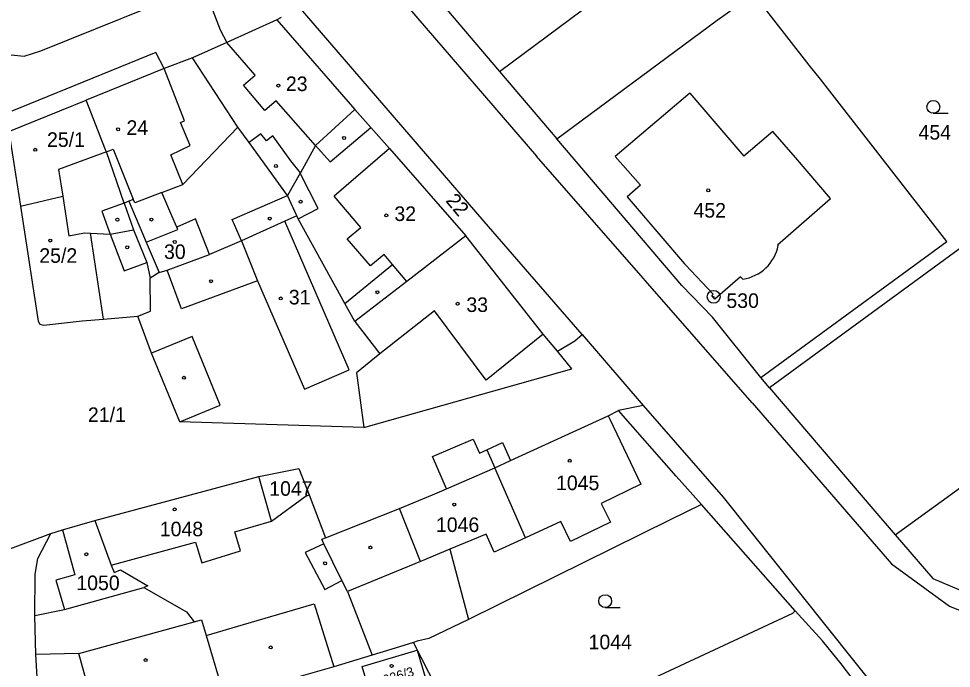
# Model space of a CAD drawing. Extents: x -736345 to -729997, y -1130177 to -1122501.
# Drawn here: x -733562.4 to -733453.6, y -1127040.9 to -1126965.1 of the extents above; entities that cross this region are included whole.
import ezdxf

# ---------------------------------------------------------------- set-up
doc = ezdxf.new("R2010")
doc.units = 0
for name, color, linetype in [('Vrstva 1', 7, 'Continuous'), ('Vrstva 17', 7, 'Continuous'), ('Vrstva 18', 7, 'Continuous'), ('Vrstva 19', 7, 'Continuous'), ('Vrstva 25', 7, 'Continuous'), ('Vrstva 4', 7, 'Continuous')]:
    doc.layers.add(name, color=color, linetype=linetype)

msp = doc.modelspace()

# ---------------------------------------------------------------- linework, layer by layer
at = {"layer": 'Vrstva 1'}
for points in [[(-733529.95, -1126948.76), (-733501.99, -1126981.18)], [(-733559.85, -1126968.91), (-733540.91, -1126961.22)], [(-733540.91, -1126961.22), (-733538.92, -1126966.43)], [(-733514.48, -1126961.65), (-733506.31, -1126971.3)], [(-733506.31, -1126971.3), (-733495.26, -1126963.12)], [(-733480.91, -1126965.32), (-733476.66, -1126962.26)], [(-733470.18, -1126970.55), (-733476.66, -1126962.26)], [(-733508.11, -1126988.8), (-733530.02, -1126963.43)], [(-733532.3, -1126965.28), (-733538.15, -1126967.92)], [(-733531.8, -1126965.01), (-733532.3, -1126965.28)], [(-733532.3, -1126965.28), (-733523.2, -1126975.75)], [(-733499.63, -1126979.17), (-733480.91, -1126965.32)], [(-733538.92, -1126966.43), (-733538.15, -1126967.92)], [(-733538.15, -1126967.92), (-733542.14, -1126969.72)], [(-733563.29, -1126969.37), (-733561.8, -1126969.5)], [(-733546.42, -1126969.09), (-733563.24, -1126975.94)], [(-733561.8, -1126969.5), (-733559.85, -1126968.91)], [(-733545.47, -1126970.94), (-733546.42, -1126969.09)], [(-733542.14, -1126969.72), (-733545.47, -1126970.94)], [(-733536.86, -1126977.79), (-733542.14, -1126969.72)], [(-733468.88, -1126972.22), (-733470.18, -1126970.55)], [(-733545.47, -1126970.94), (-733554.57, -1126974.66)], [(-733506.31, -1126971.3), (-733499.63, -1126979.17)], [(-733454.12, -1126991.13), (-733468.88, -1126972.22)], [(-733563.57, -1126978.3), (-733554.57, -1126974.66)], [(-733552.28, -1126980.44), (-733554.57, -1126974.66)], [(-733523.2, -1126975.75), (-733527.78, -1126979.95)], [(-733523.2, -1126975.75), (-733521.35, -1126977.82)], [(-733563.57, -1126978.3), (-733562.23, -1126987.02)], [(-733536.86, -1126977.79), (-733543.26, -1126984.48)], [(-733535.55, -1126979.58), (-733536.86, -1126977.79)], [(-733521.35, -1126977.82), (-733519.16, -1126980.27)], [(-733493.32, -1126986.55), (-733499.63, -1126979.17)], [(-733552.18, -1126980.67), (-733552.28, -1126980.44)], [(-733531.06, -1126985.78), (-733535.55, -1126979.58)], [(-733527.78, -1126979.95), (-733529.55, -1126983.11)], [(-733519.16, -1126980.27), (-733510.25, -1126990.48)], [(-733550.11, -1126986.66), (-733552.18, -1126980.67)], [(-733476.86, -1127009.96), (-733501.99, -1126981.18)], [(-733529.6, -1126983.18), (-733531.06, -1126985.78)], [(-733529.55, -1126983.11), (-733529.6, -1126983.18)], [(-733440.2, -1126982.91), (-733474.82, -1127008.2)], [(-733545.74, -1126985.43), (-733543.26, -1126984.48)], [(-733562.23, -1126987.02), (-733557.29, -1126985.83)], [(-733557.29, -1126985.83), (-733556.56, -1126990.46)], [(-733545.74, -1126985.43), (-733548.88, -1126986.63)], [(-733529.99, -1126988.14), (-733531.06, -1126985.78)], [(-733562.23, -1126987.02), (-733560.16, -1127000.41)], [(-733549.57, -1126986.43), (-733550.11, -1126986.66)], [(-733550.11, -1126986.66), (-733549.04, -1126989.78)], [(-733549.57, -1126986.43), (-733549.06, -1126986.21)], [(-733548.88, -1126986.63), (-733549.06, -1126986.21)], [(-733485.03, -1126996.26), (-733493.32, -1126986.55)], [(-733529.99, -1126988.14), (-733531.36, -1126988.77)], [(-733529.8, -1126988.49), (-733529.99, -1126988.14)], [(-733531.36, -1126988.77), (-733536.43, -1126991.07)], [(-733524.37, -1126998.35), (-733529.8, -1126988.49)], [(-733496.67, -1127001.99), (-733508.11, -1126988.8)], [(-733556.56, -1126990.46), (-733554.73, -1126990.12)], [(-733554.73, -1126990.12), (-733554.06, -1126990.15)], [(-733554.06, -1126990.15), (-733551.77, -1126990.26)], [(-733551.77, -1126990.26), (-733549.04, -1126989.78)], [(-733549.04, -1126989.78), (-733547.48, -1126993.57)], [(-733536.43, -1126991.07), (-733540.18, -1126992.64)], [(-733510.25, -1126990.48), (-733517.12, -1126995.78)], [(-733501.22, -1127001.93), (-733510.25, -1126990.48)], [(-733475.84, -1127007.01), (-733454.12, -1126991.13)], [(-733547.48, -1126993.57), (-733547.1, -1126995.4)], [(-733545.09, -1126994.48), (-733540.18, -1126992.64)], [(-733546.03, -1126994.76), (-733547.1, -1126995.4)], [(-733546.03, -1126994.76), (-733545.09, -1126994.48)], [(-733547.03, -1126999.25), (-733547.1, -1126995.4)], [(-733517.12, -1126995.78), (-733523.2, -1127000.47)], [(-733485.03, -1126996.26), (-733481.49, -1126999.96)], [(-733523.2, -1127000.47), (-733524.37, -1126998.35)], [(-733555, -1127000.4), (-733552.52, -1127000.18)], [(-733552.52, -1127000.18), (-733548.54, -1126999.83)], [(-733548.54, -1126999.83), (-733547.03, -1126999.25)], [(-733546.94, -1127004.15), (-733548.54, -1126999.83)], [(-733475.84, -1127007.01), (-733481.49, -1126999.96)], [(-733560.16, -1127000.41), (-733559.95, -1127000.77)], [(-733559.95, -1127000.77), (-733559.51, -1127000.9)], [(-733559.51, -1127000.9), (-733555, -1127000.4)], [(-733523.2, -1127000.47), (-733520.27, -1127004.23)], [(-733499.57, -1127003.93), (-733501.22, -1127001.93)], [(-733497.53, -1127002.71), (-733496.67, -1127001.99)], [(-733496.67, -1127001.99), (-733489.56, -1127010.26)], [(-733499.57, -1127003.93), (-733497.53, -1127002.71)], [(-733543.63, -1127012.17), (-733546.94, -1127004.15)], [(-733520.27, -1127004.23), (-733523, -1127006.45)], [(-733497.89, -1127005.97), (-733499.57, -1127003.93)], [(-733460.15, -1127025.33), (-733430.2, -1127003.66)], [(-733523, -1127006.45), (-733522.16, -1127012.84)], [(-733522.16, -1127012.84), (-733497.89, -1127005.97)], [(-733474.82, -1127008.2), (-733475.84, -1127007.01)], [(-733474.82, -1127008.2), (-733462.75, -1127022.32)], [(-733476.86, -1127009.96), (-733460.6, -1127028.73)], [(-733493.64, -1127011.45), (-733492.43, -1127010.83)], [(-733489.56, -1127010.26), (-733492.43, -1127010.83)], [(-733485.7, -1127018.48), (-733492.43, -1127010.83)], [(-733489.56, -1127010.26), (-733480.23, -1127020.96)], [(-733522.16, -1127012.84), (-733543.63, -1127012.17)], [(-733505.03, -1127016.68), (-733493.64, -1127011.45)], [(-733514.13, -1127016.21), (-733509.38, -1127014.17)], [(-733509.38, -1127014.17), (-733508.67, -1127015.81)], [(-733508.67, -1127015.81), (-733507.81, -1127015.42)], [(-733507.81, -1127015.42), (-733505.99, -1127014.59)], [(-733507.81, -1127015.42), (-733506.85, -1127017.52)], [(-733505.99, -1127014.59), (-733505.03, -1127016.68)], [(-733512.52, -1127019.96), (-733514.13, -1127016.21)], [(-733534.42, -1127018.52), (-733529.74, -1127017.6)], [(-733529.74, -1127017.6), (-733528.54, -1127020.69)], [(-733503.29, -1127025.69), (-733506.85, -1127017.52)], [(-733553.55, -1127023.65), (-733534.42, -1127018.52)], [(-733532.91, -1127023.73), (-733534.42, -1127018.52)], [(-733482.76, -1127021.79), (-733485.7, -1127018.48)], [(-733532.91, -1127023.73), (-733529.01, -1127020.87)], [(-733529.01, -1127020.87), (-733528.54, -1127020.69)], [(-733528.54, -1127020.69), (-733526.61, -1127025.68)], [(-733518.01, -1127022.28), (-733514.16, -1127020.67)], [(-733514.16, -1127020.67), (-733512.52, -1127019.96)], [(-733482.76, -1127021.79), (-733486.41, -1127023.59)], [(-733471.81, -1127034.2), (-733482.76, -1127021.79)], [(-733480.23, -1127020.96), (-733461.93, -1127043.84)], [(-733526.61, -1127025.68), (-733518.01, -1127022.28)], [(-733515.54, -1127028.44), (-733518.01, -1127022.28)], [(-733462.75, -1127022.32), (-733460.15, -1127025.33)], [(-733557.33, -1127024.75), (-733553.55, -1127023.65)], [(-733553.55, -1127023.65), (-733551.63, -1127028.89)], [(-733486.41, -1127023.59), (-733509.94, -1127035.21)], [(-733564.07, -1127027.22), (-733558.67, -1127025.18)], [(-733560.2, -1127028.1), (-733558.67, -1127025.18)], [(-733558.67, -1127025.18), (-733557.33, -1127024.75)], [(-733507.88, -1127025.27), (-733512.13, -1127027.03)], [(-733506.94, -1127027.35), (-733507.88, -1127025.27)], [(-733527.07, -1127025.86), (-733526.61, -1127025.68)], [(-733526.82, -1127026.39), (-733527.07, -1127025.86)], [(-733503.29, -1127025.69), (-733506.94, -1127027.35)], [(-733460.15, -1127025.33), (-733455.78, -1127030.43)], [(-733524.71, -1127030.68), (-733526.82, -1127026.39)], [(-733512.13, -1127027.03), (-733515.54, -1127028.44)], [(-733560.49, -1127029.92), (-733560.2, -1127028.1)], [(-733551.63, -1127028.89), (-733551.27, -1127029.74)], [(-733551.27, -1127029.74), (-733550.54, -1127029.44)], [(-733550.54, -1127029.44), (-733547.34, -1127031.29)], [(-733460.6, -1127028.73), (-733453.82, -1127033.66)], [(-733560.53, -1127034.75), (-733560.49, -1127029.92)], [(-733524.06, -1127031.96), (-733524.71, -1127030.68)], [(-733455.78, -1127030.43), (-733438.11, -1127037.9)], [(-733557.08, -1127034.03), (-733547.83, -1127031.5)], [(-733547.34, -1127031.29), (-733547.83, -1127031.5)], [(-733547.83, -1127031.5), (-733542.85, -1127034.33)], [(-733524.06, -1127031.96), (-733521.2, -1127039.39)], [(-733453.82, -1127033.66), (-733437.72, -1127040.1)], [(-733560.53, -1127034.75), (-733557.08, -1127034.03)], [(-733560.41, -1127039.29), (-733560.53, -1127034.75)], [(-733542.85, -1127034.33), (-733541.96, -1127035.5)], [(-733472.14, -1127034.5), (-733508.86, -1127051.61)], [(-733471.81, -1127034.2), (-733472.14, -1127034.5)], [(-733468.65, -1127037.72), (-733471.81, -1127034.2)], [(-733541.96, -1127035.5), (-733541.11, -1127035.27)], [(-733541.11, -1127035.27), (-733540.57, -1127037.09)], [(-733509.94, -1127035.21), (-733514.57, -1127037.42)], [(-733540.57, -1127037.09), (-733538.42, -1127044.31)], [(-733516.37, -1127037.89), (-733519, -1127038.71)], [(-733515.94, -1127037.76), (-733516.37, -1127037.89)], [(-733509.26, -1127051.8), (-733516.37, -1127037.89)], [(-733514.57, -1127037.42), (-733515.94, -1127037.76)], [(-733466.47, -1127040.39), (-733468.65, -1127037.72)], [(-733555.4, -1127039.19), (-733560.41, -1127039.29)], [(-733559.75, -1127050.58), (-733560.41, -1127039.29)], [(-733552.86, -1127048.48), (-733555.4, -1127039.19)], [(-733521.2, -1127039.39), (-733525.66, -1127040.73)], [(-733522.34, -1127040.71), (-733515.95, -1127038.8)], [(-733519, -1127038.71), (-733521.2, -1127039.39)], [(-733515.95, -1127038.8), (-733514.9, -1127042.32)], [(-733462.37, -1127045.74), (-733466.47, -1127040.39)], [(-733525.66, -1127040.73), (-733533.01, -1127042.82)], [(-733521.29, -1127044.23), (-733522.34, -1127040.71)]]:
    msp.add_lwpolyline(points, dxfattribs=at)
at = {"layer": 'Vrstva 25'}
for points in [[(-733455.71, -1126976.18), (-733453.96, -1126976.18)], [(-733493.99, -1127033.82), (-733492.24, -1127033.82)]]:
    msp.add_lwpolyline(points, dxfattribs=at)
for centre, radius in [((-733532.13, -1126972.94), 0.175), ((-733455.71, -1126975.43), 0.75), ((-733550.83, -1126978.05), 0.175), ((-733524.45, -1126979.06), 0.175), ((-733560.5, -1126980.43), 0.175), ((-733532.41, -1126982.33), 0.175), ((-733481.97, -1126985.17), 0.175), ((-733529.53, -1126986.5), 0.175), ((-733533.13, -1126988.46), 0.175), ((-733519.53, -1126988.09), 0.175), ((-733550.91, -1126988.59), 0.175), ((-733546.93, -1126988.57), 0.175), ((-733558.75, -1126991.02), 0.175), ((-733544.21, -1126991.19), 0.175), ((-733549.76, -1126991.81), 0.175), ((-733539.97, -1126995.76), 0.175), ((-733520.57, -1126997.05), 0.175), ((-733481.33, -1126997.58), 0.75), ((-733531.85, -1126997.77), 0.175), ((-733481.33, -1126997.58), 0.032), ((-733511.21, -1126998.4), 0.175), ((-733543.15, -1127007.02), 0.175), ((-733498.12, -1127016.71), 0.175), ((-733511.61, -1127021.81), 0.175), ((-733544.23, -1127022.38), 0.175), ((-733554.53, -1127027.6), 0.175), ((-733521.38, -1127026.81), 0.175), ((-733526.67, -1127028.66), 0.175), ((-733493.99, -1127033.07), 0.75), ((-733533.02, -1127038.47), 0.175), ((-733547.62, -1127039.95), 0.175), ((-733518.91, -1127040.62), 0.175)]:
    msp.add_circle(centre, radius, dxfattribs=at)
at = {"layer": 'Vrstva 4'}
for points in [[(-733534.85, -1126971.75), (-733538.15, -1126967.92)], [(-733543.07, -1126977.06), (-733545.47, -1126970.94)], [(-733536.21, -1126972.92), (-733534.85, -1126971.75)], [(-733533.69, -1126975.85), (-733536.21, -1126972.92)], [(-733484.12, -1126973.85), (-733492.82, -1126981.22)], [(-733484.12, -1126973.85), (-733477.81, -1126981.2)], [(-733532.37, -1126974.71), (-733533.69, -1126975.85)], [(-733527.78, -1126979.95), (-733532.37, -1126974.71)], [(-733543.56, -1126977.25), (-733543.07, -1126977.06)], [(-733542.42, -1126979.94), (-733543.56, -1126977.25)], [(-733526.08, -1126981.83), (-733521.35, -1126977.82)], [(-733474.44, -1126978.3), (-733477.81, -1126981.2)], [(-733471.78, -1126981.34), (-733474.44, -1126978.3)], [(-733534.16, -1126978.59), (-733535.55, -1126979.58)], [(-733533.53, -1126979.4), (-733534.16, -1126978.59)], [(-733532.78, -1126978.82), (-733533.53, -1126979.4)], [(-733530.66, -1126981.72), (-733532.78, -1126978.82)], [(-733552.18, -1126980.67), (-733551.41, -1126980.36)], [(-733551.41, -1126980.36), (-733549.06, -1126986.21)], [(-733544.68, -1126981.04), (-733542.42, -1126979.94)], [(-733527.78, -1126979.95), (-733526.08, -1126981.83)], [(-733519.16, -1126980.27), (-733525.61, -1126985.86)], [(-733552.18, -1126980.67), (-733557.78, -1126982.74)], [(-733543.26, -1126984.48), (-733544.68, -1126981.04)], [(-733529.55, -1126983.11), (-733530.66, -1126981.72)], [(-733492.82, -1126981.22), (-733489.86, -1126984.55)], [(-733467.7, -1126986.13), (-733471.78, -1126981.34)], [(-733557.78, -1126982.74), (-733557.29, -1126985.83)], [(-733527.48, -1126987.3), (-733529.6, -1126983.18)], [(-733489.86, -1126984.55), (-733491.42, -1126985.94)], [(-733544.55, -1126988.12), (-733545.74, -1126985.43)], [(-733537.52, -1126988.58), (-733531.06, -1126985.78)], [(-733522.51, -1126989.51), (-733525.61, -1126985.86)], [(-733491.42, -1126985.94), (-733490.74, -1126986.73)], [(-733550.11, -1126986.66), (-733552.72, -1126987.61)], [(-733549.57, -1126986.43), (-733547.54, -1126991.2)], [(-733490.74, -1126986.73), (-733484.75, -1126993.72)], [(-733473.88, -1126991.51), (-733467.7, -1126986.13)], [(-733552.72, -1126987.61), (-733551.77, -1126990.26)], [(-733543.97, -1126989.45), (-733544.55, -1126988.12)], [(-733529.8, -1126988.49), (-733527.48, -1126987.3)], [(-733541.8, -1126988.5), (-733543.97, -1126989.45)], [(-733540.18, -1126992.64), (-733541.8, -1126988.5)], [(-733536.43, -1126991.07), (-733537.52, -1126988.58)], [(-733523.88, -1127006.11), (-733531.36, -1126988.77)], [(-733552.52, -1127000.18), (-733554.06, -1126990.15)], [(-733551.77, -1126990.26), (-733550.12, -1126994.55)], [(-733547.54, -1126991.2), (-733543.85, -1126989.73)], [(-733543.85, -1126989.73), (-733543.97, -1126989.45)], [(-733524.08, -1126990.84), (-733522.51, -1126989.51)], [(-733547.54, -1126991.2), (-733546.03, -1126994.76)], [(-733536.43, -1126991.07), (-733534.57, -1126995.71)], [(-733521.37, -1126993.98), (-733524.08, -1126990.84)], [(-733473.88, -1126991.51), (-733473.79, -1126991.61)], [(-733550.12, -1126994.55), (-733547.48, -1126993.57)], [(-733519.78, -1126992.64), (-733521.37, -1126993.98)], [(-733518.8, -1126993.82), (-733519.78, -1126992.64)], [(-733484.75, -1126993.72), (-733484.63, -1126993.86)], [(-733543.43, -1126998.97), (-733545.09, -1126994.48)], [(-733524.37, -1126998.35), (-733518.8, -1126993.82)], [(-733517.12, -1126995.78), (-733518.8, -1126993.82)], [(-733484.63, -1126993.86), (-733481.39, -1126997.29)], [(-733534.57, -1126995.71), (-733543.43, -1126998.97)], [(-733534.57, -1126995.71), (-733529.06, -1127008.37)], [(-733478.19, -1126995.24), (-733481.21, -1126997.85)], [(-733478.19, -1126995.24), (-733477.94, -1126995.54)], [(-733481.56, -1126997.44), (-733481.39, -1126997.29)], [(-733481.21, -1126997.85), (-733481.56, -1126997.44)], [(-733513.92, -1126999.23), (-733520.27, -1127004.23)], [(-733507.88, -1127007.29), (-733513.92, -1126999.23)], [(-733542.17, -1127002.21), (-733546.94, -1127004.15)], [(-733538.92, -1127010.22), (-733542.17, -1127002.21)], [(-733501.22, -1127001.93), (-733507.88, -1127007.29)], [(-733529.06, -1127008.37), (-733523.88, -1127006.11)], [(-733543.63, -1127012.17), (-733538.92, -1127010.22)], [(-733493.64, -1127011.45), (-733493.45, -1127011.86)], [(-733493.45, -1127011.86), (-733489.84, -1127019.45)], [(-733512.52, -1127019.96), (-733506.85, -1127017.52)], [(-733506.85, -1127017.52), (-733505.03, -1127016.68)], [(-733489.84, -1127019.45), (-733494.45, -1127021.67)], [(-733494.45, -1127021.67), (-733493.39, -1127023.86)], [(-733537.2, -1127024.99), (-733532.91, -1127023.73)], [(-733499.16, -1127023.8), (-733503.29, -1127025.69)], [(-733498.03, -1127026.12), (-733499.16, -1127023.8)], [(-733493.39, -1127023.86), (-733498.03, -1127026.12)], [(-733557.33, -1127024.75), (-733555.89, -1127030)], [(-733536.55, -1127027.22), (-733537.2, -1127024.99)], [(-733551.63, -1127028.89), (-733541.79, -1127026.2)], [(-733541.79, -1127026.2), (-733541.05, -1127028.6)], [(-733541.05, -1127028.6), (-733536.55, -1127027.22)], [(-733526.82, -1127026.39), (-733528.98, -1127027.42)], [(-733528.98, -1127027.42), (-733526.72, -1127031.71)], [(-733512.13, -1127027.03), (-733509.94, -1127035.21)], [(-733515.54, -1127028.44), (-733524.06, -1127031.96)], [(-733555.89, -1127030), (-733558.1, -1127030.61)], [(-733558.1, -1127030.61), (-733557.08, -1127034.03)], [(-733526.72, -1127031.71), (-733524.71, -1127030.68)], [(-733536.18, -1127035.8), (-733527.96, -1127033.38)], [(-733527.96, -1127033.38), (-733525.66, -1127040.73)], [(-733555.4, -1127039.19), (-733541.96, -1127035.5)], [(-733540.57, -1127037.09), (-733536.18, -1127035.8)]]:
    msp.add_lwpolyline(points, dxfattribs=at)
msp.add_arc((-733478.729, -1126990.551), 5.051, 278.989, 347.90971, dxfattribs=at)

# ---------------------------------------------------------------- texts
at = {"layer": 'Vrstva 17'}
msp.add_text('530', height=1.7, dxfattribs=at).set_placement((-733479.85, -1126998.88))
at = {"layer": 'Vrstva 18'}
for s, p in [('454', (-733457.43, -1126979.25)), ('21/1', (-733554.35, -1127012.18)), ('1047', (-733533.19, -1127020.79)), ('1044', (-733495.93, -1127038.69))]:
    msp.add_text(s, height=1.7, dxfattribs=at).set_placement(p)
msp.add_text('22', height=1.7, rotation=309.90246, dxfattribs=at).set_placement((-733512.689, -1126986.405))
at = {"layer": 'Vrstva 19'}
for s, p in [('23', (-733531.25, -1126973.59)), ('24', (-733549.85, -1126978.7)), ('25/1', (-733559.12, -1126980.1)), ('32', (-733518.59, -1126988.74)), ('452', (-733483.69, -1126988.35)), ('30', (-733545.47, -1126993.17)), ('25/2', (-733560.02, -1126993.62)), ('31', (-733530.91, -1126998.47)), ('33', (-733510.19, -1126999.35)), ('1045', (-733499.73, -1127020.13)), ('1048', (-733545.96, -1127025.51)), ('1046', (-733513.74, -1127025.01)), ('1050', (-733555.7, -1127031.79))]:
    msp.add_text(s, height=1.7, dxfattribs=at).set_placement(p)
msp.add_text('1036/3', height=1.1, rotation=16.90013, dxfattribs=at).set_placement((-733520.507, -1127043.061))

doc.saveas('drawing.dxf')
